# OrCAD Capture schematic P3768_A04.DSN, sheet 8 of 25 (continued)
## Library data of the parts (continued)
U59 = U_SW_LOAD#1: ASSEMBLY: HDMI; CDS_LIB: analog; CDS_PART_NAME: U_SW_LOAD_SOT363-GS7616SC-R,-9999V..9999V,-9999V..9999V,9999A,SWITCH,115-1566-000; CDS_PHYS_PART_NAME: U_SW_LOAD_SOT363-GS7616SC-R,-9999V..9999V,-9999V..9999V,9999A,SWITCH,115-1566-000-115-1566-000; CDS_SEC: 1; DEVICE_TYPENAME: U_SW_LOAD_SOT363-GS7616SC-R-9999V9999V-9999V9999V9999ASWITCH115-1566-000-115-1566-000; DRAWING: @P3768_A04_LIB.P3768_A04(SCH_1):PAGE17; MAX_CURRENT: 9999A; MAX_VOLTAGE: -9999V..9999V; NV_NAME: GS7616SC-R; NV_PN: 115-1566-000; OUTPUT_VOLTAGE: -9999V..9999V; PACK_TYPE: SOT363; PATH: I358; PHYS_PAGE: 17; ROT: 0; SEC: 1; TYPE: Switch; VER: 4; XY: (-9450,6750)
U60 = U_POWER_SW: ASSEMBLY: HDMI; CDS_LIB: power_supply; CDS_PART_NAME: U_POWER_SW_SOT23_5B-GS7612S5MC-R,2V..5.5V,2V..5.5V,1.6A,SWITCH,315-0992-000; CDS_PHYS_PART_NAME: U_POWER_SW_SOT23_5B-GS7612S5MC-R,2V..5.5V,2V..5.5V,1.6A,SWITCH,315-0992-000-315-0992-000; CDS_SEC: 1; DEVICE_TYPENAME: U_POWER_SW_SOT23_5B-GS7612S5MC-R2V55V2V55V16ASWITCH315-0992-000-315-0992-000; DRAWING: @P3768_A04_LIB.P3768_A04(SCH_1):PAGE17; MAX_CURRENT: 1.6A; MAX_VOLTAGE: 2V..5.5V; NV_NAME: GS7612S5MC-R; NV_PN: 315-0992-000; OUTPUT_VOLTAGE: 2V..5.5V; PACK_TYPE: SOT23_5B; PATH: I348; PHYS_PAGE: 17; ROT: 0; SEC: 1; TYPE: Switch; VER: 7; XY: (-6650,6550)

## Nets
GND: C102.2 C105.2 C174.2 C236.2 C359.1 C360.2 C361.1 C362.2 C363.2 C366.2 C367.2 C368.2 C369.2 C370.2 C439.2 C440.2 C441.2 C442.2 D21.3(GND1) D22.3(GND1) D23.3(GND1) J8.2(GND_1) J8.5(GND_2) J8.8(GND_3) J8.11(GND_4) J8.16(GND_7) J8.19(PWR_RET) J8.21(SHIELD4) J8.22(SHIELD2) J8.23(SHIELD3) J8.24(SHIELD1) J25.2(D2_SHIELD) J25.5(D1_SHIELD) J25.8(D0_SHIELD) J25.11(CK_SHIELD) J25.17(DDC_CEC_GND) J25.20(SHIELD1) J25.21(SHIELD2) J25.22(SHIELD3) J25.23(SHIELD4) Q58.2(S) R306.2 R445.2 R544.2 R550.2 U10.2(GND) U49.3(GND) U50.6(GND) U59.4(GND) U60.2(GND) ; also on sheet 1 2 3 4 5 6 7 9 10 11 12 13 14 15 16 17 18 19 21 25
VDD_1V8: C359.2 C361.2 U49.5(VCC) U50.9(VREF1) ; also on sheet 1 2 3 5 12 14 19 21
VDD_3V3_DP: C105.1 C174.1 C362.1 C363.1 J8.20(PWR) R445.1 R557.1 U10.1(OUT)
VDD_3V3_HDMI: Q52.1(G) Q58.1(G) R447.1 R448.1 R550.1 U59.1(VOUT1) U59.2(VOUT2) U60.4(EN)
VDD_3V3_SYS: C236.1 C360.1 U10.5(IN) U59.5(VIN1) U59.6(VIN2) ; also on sheet 1 2 3 4 5 6 7 11 12 14 15 19 20 21
VDD_5V0_HDMI_CON: C441.1 C442.1 J25.18(5V) R558.1 R559.1 R998.1 R999.1 U60.1(OUT)
VDD_5V_SYS: C439.1 C440.1 U60.5(IN) ; also on sheet 1 2 9 10 11 12 13 14 15 16 17 21
BUCK_3V3_PG: R91.2 ; also on sheet 11 13 14 15
DP1_AUX_N: U50.8(AUX1_N) ; also on sheet 19
DP1_AUX_P: U50.7(AUX1_P) ; also on sheet 19
DP1_HPD: R444.1 U49.4(Q*) ; also on sheet 19
DP1_TXD0_N: C97.1 C434.1 ; also on sheet 19
DP1_TXD0_P: C101.1 C438.1 ; also on sheet 19
DP1_TXD1_N: C96.1 C433.1 ; also on sheet 19
DP1_TXD1_P: C100.1 C437.1 ; also on sheet 19
DP1_TXD2_N: C95.1 C432.1 ; also on sheet 19
DP1_TXD2_P: C99.1 C436.1 ; also on sheet 19
DP1_TXD3_N: C94.1 C431.1 ; also on sheet 19
DP1_TXD3_P: C98.1 C435.1 ; also on sheet 19
DP_CON_AUX_C_N: C364.1 U50.12(AUX2A_N)
DP_CON_AUX_C_P: C365.1 U50.3(AUX2A_P)
DP_CON_AUX_N: C364.2 C366.1 D21.4(3A) D21.7(3B) J8.17(AUXN) R547.1 R998.2 U50.1(AUX2B_N)
DP_CON_AUX_P: C365.2 C367.1 D21.5(4A) D21.6(4B) J8.15(AUXP) R551.1 R999.2 U50.2(AUX2B_P)
DP_CON_LANE0_N: D22.4(3A) D22.7(3B) J8.3(LANE_0N) L18.2 R83.2
DP_CON_LANE0_P: D22.5(4A) D22.6(4B) J8.1(LANE_0P) L18.1 R84.2
DP_CON_LANE0_R_N: C97.2 L18.3 R83.1
DP_CON_LANE0_R_P: C101.2 L18.4 R84.1
DP_CON_LANE1_N: D22.1(1A) D22.10(1B) J8.6(LANE_1N) L17.2 R81.2
DP_CON_LANE1_P: D22.2(2A) D22.9(2B) J8.4(LANE_1P) L17.1 R82.2
DP_CON_LANE1_R_N: C96.2 L17.3 R81.1
DP_CON_LANE1_R_P: C100.2 L17.4 R82.1
DP_CON_LANE2_N: D23.4(3A) D23.7(3B) J8.9(LANE_2N) L16.2 R79.2
DP_CON_LANE2_P: D23.5(4A) D23.6(4B) J8.7(LANE_2P) L16.1 R80.2
DP_CON_LANE2_R_N: C95.2 L16.3 R79.1
DP_CON_LANE2_R_P: C99.2 L16.4 R80.1
DP_CON_LANE3_N: D23.1(1A) D23.10(1B) J8.12(LANE_3N) L15.2 R77.2
DP_CON_LANE3_P: D23.2(2A) D23.9(2B) J8.10(LANE_3P) L15.1 R78.2
DP_CON_LANE3_R_N: C94.2 L15.3 R77.1
DP_CON_LANE3_R_P: C98.2 L15.4 R78.1
DP_HPD_CON: C369.1 D21.1(1A) D21.10(1B) J8.18(HPD) J25.19(HP_DET) R446.2
DP_HPD_CON_R: C368.1 R446.1 U50.11(HPD2)
DP_HPD_INV: R444.2 U49.2(I) U50.5(HPD1)
DP_MODE: J8.13(MODE) R559.2 U50.4(SEL)
DP_SW_EN: R91.1 U10.4(EN)
HDMI_CEC: D85.2(A2) Q52.2(S) R447.2 ; also on sheet 19
HDMI_CEC_CON: C370.1 J8.14(CEC) R306.1 R449.2 R552.1
HDMI_CEC_CON_R: J25.13(CEC) R552.2
HDMI_CEC_Q: D85.3(CC) Q52.3(D) R449.1
HDMI_CEC_Q_D: D85.1(A1) R448.2
HDMI_TXC_R_N: C431.2 J25.12(CK*) R556.1
HDMI_TXC_R_P: C435.2 J25.10(CK) R555.1
HDMI_TXD0_R_N: C432.2 J25.9(D0*) R554.1
HDMI_TXD0_R_P: C436.2 J25.7(D0) R553.1
HDMI_TXD1_R_N: C433.2 J25.6(D1*) R549.1
HDMI_TXD1_R_P: C437.2 J25.4(D1) R548.1
HDMI_TXD2_R_N: C434.2 J25.3(D2*) R546.1
HDMI_TXD2_R_P: C438.2 J25.1(D2) R545.1
IFP_SCL: J25.15(SCL) R551.2
IFP_SDA: J25.16(SDA) R547.2
IFP_TERM: Q58.3(D) R545.2 R546.2 R548.2 R549.2 R553.2 R554.2 R555.2 R556.2
MOD_SLEEP*: R544.1 U59.3(EN) ; also on sheet 1 21
SNN_D21_PIN2: D21.2(2A) D21.9(2B)
SNN_DP_LSW_OC: U10.3(OC*)
SNN_HDMI_LSW_OC: U60.3(OC*)
SNN_HDMI_RSVD1: J25.14(RESERVED)
U50_VREF2: C102.1 R557.2 R558.2 U50.10(VREF2)

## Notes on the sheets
sheet 8
- A
- B
- C
- D
- E
- F
- G
- H
- DisplayPort/HDMI Connector
- PLACE NEAR DP CON
- PLACE NEAR HDMI CON
- 1
- 1
- 1.5~5.5V
- EN VINH = 1.2V
- 1.6A limit
- 2
- 2
- place close to connector
- PCB CO-LAYOUT
- PCB CO-LAYOUT
- PCB CO-LAYOUT
- PCB CO-LAYOUT
- Pin 14 of DP connector
- 3
- may be weakly pulled down
- 3
- in the Dual-mode Device
- that supports both
- DisplayPort 1.1a and HDMI
- PCB CO-LAYOUT
- PCB CO-LAYOUT
- PCB CO-LAYOUT
- PCB CO-LAYOUT
- PCB CO-LAYOUT
- PCB CO-LAYOUT
- PCB CO-LAYOUT
- 4
- 4
- PCB CO-LAYOUT
- PCB CO-LAYOUT
- 5
- 5
- NVIDIA CORPORATION
- 2701 SAN TOMAS EXPRESSWAY
- SANTA CLARA, CA 95050, USA
- ASSEMBLY
- <ASSEMBLY_DESCRIPTION>
- PAGE DETAIL
- DISPLAYPORT/HDMI
- 600-13768-BASE-400
- NV_PN
- ALL NVIDIA DESIGN SPECIFICATIONS, REFERENCE SPECIFICATIONS, REFERENCE BOARDS, FILES, DRAWINGS, DIAGNOSTICS, LISTS AND OTHER DOCUMENTS OR INFORMATION (TOGETHER AND SEPARATELY, 'MATERIALS') ARE BEING PROVIDED 'AS IS'. THE MATERIALS MAY
- P3768-A04
- 17 OF 25
- CONTAIN KNOWN AND UNKNOWN VIOLATIONS OR DEVIATIONS OF INDUSTRY STANDARDS AND SPECIFICATIONS. NVIDIA MAKES NO WARRANTIES, EXPRESSED, IMPLIED, STATUTORY OR OTHERWISE WITH RESPECT TO THE MATERIALS OR OTHERWISE, AND EXPRESSLY DISCLAIMS ALL
- PCB REV
- PAGE
- IMPLIED WARRANTIES INCLUDING, WITHOUT LIMITATION, THE WARRANTIES OF DESIGN, OF NONINFRINGEMENT, MERCHANTABILITY OR FITNESS FOR A PARTICULAR PURPOSE, OR ARISING FROM A COURSE OF DEALING, TRADE USAGE, TRADE PRACTICE, OR INDUSTRY STANDARDS.
- BOM REV
- A
- DATE
- 27-FEB-2023
- A
- B
- C
- D
- E
- F
- G
- H
